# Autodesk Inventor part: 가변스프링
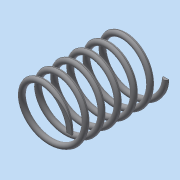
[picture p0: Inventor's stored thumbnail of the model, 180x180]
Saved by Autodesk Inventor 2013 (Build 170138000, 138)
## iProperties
Created: 2020-09
Part Number: 가변스프링
Material: 스테인리스강
Document SubType Name: 판금
Designer: dgall
Density: 8.08 g/cm^3
Sheet Metal Rule: 기본값
Author: dgall
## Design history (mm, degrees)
sketch "스케치1"
  geometry: L1 (0, 0)-(-10, 0); L2 (-10, 0)-(-10, 26.7); L3 (-10, 26.7)-(0, 26.7); C1 r 1 at (0, 0)
  constraints: 6 end point, 1 centre point, 1 coincident, 1 horizontal, 1 parallel, 1 perpendicular, 1 vertical alignment
  dimensions: "d0" = 26.7 distance of L1.end L2.end (derived); "d3" = 2 diameter of C1; "d4" = 20 diameter of L3.end L2
feature "코일1" sketch "스케치1" pitch "d5" = 10; turns "d7" = 6; dims "d6" = 26.7 (= d0), "d8" = 0, angle "d9" = 90 deg, angle "d10" = 90 deg, "d11" = 0, "d12" = 0
feature "분할1"
node "작업 평면1"
feature "분할2"
node "솔리드1"
other parameters: "d13" = 0, "K계수" = 4.4, "BendRadius" = 0.5 (derived), "BendReliefWidth" = 0.5 (derived), "BendReliefDepth" = 0.25 (derived), "CornerReliefSize" = 2 (derived), "SeamGap" = 0.01, "MinimumRemnant" = 1 (derived), "TransitionRadius" = 0.5 (= BendRadius)
